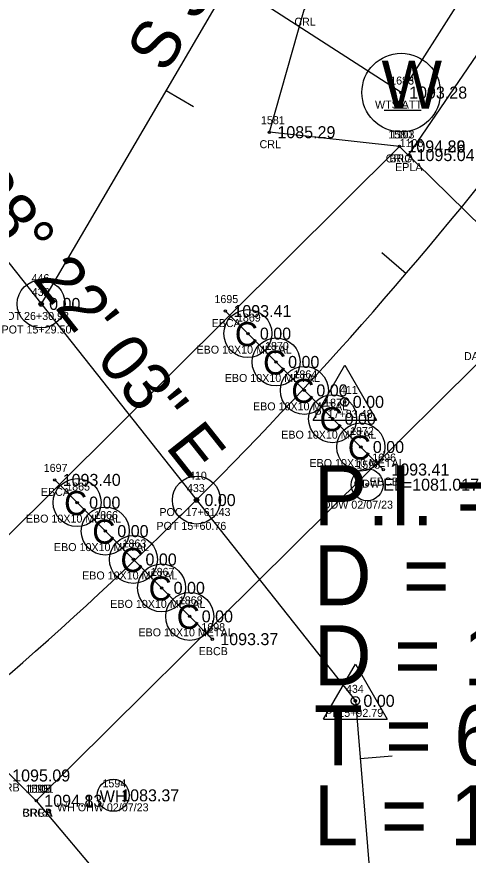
# Model space of a CAD drawing. Extents: x 1539151 to 1541799, y 1198646 to 1201165.
# Drawn here: x 1540107.9 to 1540164.3, y 1199420.8 to 1199525.6 of the extents above; entities that cross this region are included whole.
import ezdxf

# ---------------------------------------------------------------- set-up
doc = ezdxf.new("R2010")
doc.units = 0
for name, color, linetype in [('RD_EX_Bridge', 7, 'Continuous'), ('RD_EX_Bridge_txCode', 7, 'Continuous'), ('RD_EX_Driveway_txCode', 7, 'Continuous'), ('RD_EX_H2O', 7, 'Continuous'), ('RD_EX_H2O_txCode', 7, 'Continuous'), ('RD_EX_Road', 7, 'Continuous'), ('RD_EX_Road_txCode', 7, 'Continuous'), ('RD_EX_TX_Bridge_ELEV', 7, 'Continuous'), ('RD_EX_TX_H2O_ELEV', 7, 'Continuous'), ('RD_EX_TX_Road_ELEV', 7, 'Continuous'), ('RD_EX_TX_UT_ELEV', 7, 'Continuous'), ('RD_EX_TX_VEG_ELEV', 7, 'Continuous'), ('RD_EX_UT', 7, 'Continuous'), ('RD_EX_UT_txCode', 7, 'Continuous'), ('RD_EX_VEG', 7, 'Continuous'), ('RD_EX_VEG_txCode', 7, 'Continuous'), ('RD_HC_Cl', 7, 'Continuous'), ('RD_HC_Data', 7, 'Continuous'), ('RD_HC_Data_Tic', 7, 'Continuous'), ('RD_HC_Survey_ELEV', 7, 'Continuous'), ('RD_HC_txCode', 7, 'Continuous'), ('RD_SMD_Locator', 7, 'Continuous')]:
    doc.layers.add(name, color=color, linetype=linetype)

msp = doc.modelspace()

# ---------------------------------------------------------------- linework, layer by layer
at = {"layer": 'RD_EX_Bridge'}
for p, q in [((1540133.96, 1199488.77), (1540153.7, 1199468.96)), ((1540112.62, 1199467.67), (1540132.32, 1199447.76))]:
    msp.add_line(p, q, dxfattribs=at)
msp.add_lwpolyline([(1540110.32, 1199427.56), (1540091.92, 1199445.97), (1540155.71, 1199509.35), (1540174.37, 1199491.07), (1540110.32, 1199427.56)], dxfattribs=at)
for centre in [(1540136.77, 1199485.95), (1540140.3, 1199482.41), (1540143.83, 1199478.86), (1540147.36, 1199475.32), (1540150.89, 1199471.78), (1540115.43, 1199464.83), (1540118.95, 1199461.27), (1540122.47, 1199457.72), (1540125.99, 1199454.17), (1540129.5, 1199450.61)]:
    msp.add_circle(centre, 3, dxfattribs=at)
at = {"layer": 'RD_EX_H2O'}
for points in [[(1540155.71, 1199509.35), (1540139.46, 1199511.13), (1540143.81, 1199526.44), (1540162.16, 1199549.57), (1540173.51, 1199542.73), (1540200.09, 1199580.59)], [(1540110.32, 1199427.56), (1540119.33, 1199416.8), (1540132.83, 1199393.98), (1540138.31, 1199358.3), (1540135.73, 1199340.81)]]:
    msp.add_lwpolyline(points, dxfattribs=at)
for centre, radius in [((1540151.68, 1199467.07), 2), ((1540151.68, 1199467.07), 0.15), ((1540119.94, 1199428.24), 2), ((1540119.94, 1199428.24), 0.005)]:
    msp.add_circle(centre, radius, dxfattribs=at)
at = {"layer": 'RD_EX_Road'}
msp.add_lwpolyline([(1540156.86, 1199508.27), (1540186.51, 1199551.73), (1540214.32, 1199591.31), (1540249.72, 1199632.22), (1540286.8, 1199666.61), (1540324.36, 1199693.31), (1540344.92, 1199710.43), (1540367.33, 1199727.77), (1540402.7, 1199760.37), (1540437.37, 1199795.58), (1540455.74, 1199815.52), (1540466.15, 1199827.23), (1540503.86, 1199868.5), (1540538.69, 1199906.78), (1540571.44, 1199944.18), (1540603.42, 1199982.61), (1540638.15, 1200019.15), (1540672.1, 1200056.68), (1540705.32, 1200094.04), (1540739.01, 1200131.56)], dxfattribs=at)
at = {"layer": 'RD_EX_UT'}
msp.add_line((1540153.8, 1199513.88), (1540158.43, 1199513.88), dxfattribs=at)
msp.add_circle((1540155.93, 1199516.08), 4.91, dxfattribs=at)
at = {"layer": 'RD_EX_VEG'}
msp.add_lwpolyline([(1540712.01, 1200109.09), (1540564.8, 1199952.12), (1540511.25, 1199924.62), (1540488.55, 1199863.43), (1540394.02, 1199755.91), (1540277.54, 1199671.42), (1540233.54, 1199628.53), (1540200.18, 1199585.62), (1540155.93, 1199516.08), (1540069.9, 1199571.55)], dxfattribs=at)
at = {"layer": 'RD_HC_Cl'}
for p, q in [((1540172.44, 1199594.87), (1540110.93, 1199489.66)), ((1540078.23, 1199530.97), (1540150.21, 1199440.05)), ((1540150.21, 1199440.05), (1540160.06, 1199322.6))]:
    msp.add_line(p, q, dxfattribs=at)
msp.add_arc((1539789.52, 1199807.08), 482.77, 309.3443, 325.5923, dxfattribs=at)
at = {"layer": 'RD_HC_Data'}
for p, q in [((1540144.91, 1199475.13), (1540148.88, 1199482.01)), ((1540148.88, 1199482.01), (1540152.85, 1199475.13)), ((1540144.91, 1199475.13), (1540152.85, 1199475.13)), ((1540146.24, 1199437.75), (1540150.21, 1199444.63)), ((1540150.21, 1199444.63), (1540154.18, 1199437.75)), ((1540146.24, 1199437.75), (1540154.18, 1199437.75))]:
    msp.add_line(p, q, dxfattribs=at)
for centre, radius in [((1540110.93, 1199489.66), 3), ((1540110.93, 1199489.66), 3), ((1540110.93, 1199489.66), 0.282), ((1540110.93, 1199489.66), 0.282), ((1540148.88, 1199477.42), 0.529), ((1540130.34, 1199465.15), 3), ((1540130.34, 1199465.15), 3), ((1540130.34, 1199465.15), 0.282), ((1540130.34, 1199465.15), 0.282), ((1540150.21, 1199440.05), 0.529)]:
    msp.add_circle(centre, radius, dxfattribs=at)
at = {"layer": 'RD_HC_Data_Tic'}
for p, q in [((1540126.54, 1199516.36), (1540129.99, 1199514.34)), ((1540156.54, 1199493.44), (1540153.5, 1199496.04)), ((1540150.82, 1199432.86), (1540154.8, 1199433.19))]:
    msp.add_line(p, q, dxfattribs=at)
at = {"layer": 'RD_SMD_Locator'}
for centre in [(1540155.93, 1199516.08), (1540155.93, 1199516.08), (1540139.46, 1199511.13), (1540155.71, 1199509.35), (1540155.71, 1199509.35), (1540156.86, 1199508.27), (1540110.93, 1199489.66), (1540110.93, 1199489.66), (1540133.96, 1199488.77), (1540136.77, 1199485.95), (1540140.3, 1199482.41), (1540143.83, 1199478.86), (1540148.88, 1199477.42), (1540147.36, 1199475.32), (1540150.89, 1199471.78), (1540153.7, 1199468.96), (1540112.62, 1199467.67), (1540130.34, 1199465.15), (1540130.34, 1199465.15), (1540115.43, 1199464.83), (1540118.95, 1199461.27), (1540122.47, 1199457.72), (1540125.99, 1199454.17), (1540129.5, 1199450.61), (1540132.32, 1199447.76), (1540150.21, 1199440.05), (1540110.32, 1199427.56), (1540110.32, 1199427.56), (1540110.32, 1199427.56)]:
    msp.add_circle(centre, 0.15, dxfattribs=at)

# ---------------------------------------------------------------- texts
at = {"layer": 'RD_EX_Bridge'}
for p in [(1540135.14, 1199484.39), (1540138.67, 1199480.84), (1540142.2, 1199477.3), (1540145.73, 1199473.76), (1540149.26, 1199470.22), (1540113.8, 1199463.27), (1540117.32, 1199459.71), (1540120.84, 1199456.16), (1540124.36, 1199452.6), (1540127.87, 1199449.05)]:
    msp.add_text('C', height=3, dxfattribs=at).set_placement(p)
at = {"layer": 'RD_EX_Bridge_txCode'}
for s, p in [('1103', (1540154.61, 1199510.35)), ('BRC', (1540154.46, 1199507.35)), ('1695', (1540132.59, 1199489.77)), ('1869', (1540135.4, 1199487.45)), ('EBCA', (1540132.24, 1199486.77)), ('EBO 10X10 METAL', (1540130.35, 1199483.45)), ('1870', (1540138.91, 1199483.91)), ('EBO 10X10 METAL', (1540133.88, 1199479.91)), ('1864', (1540142.46, 1199480.36)), ('1871', (1540146.3, 1199476.82)), ('EBO 10X10 METAL', (1540137.41, 1199476.36)), ('EBO 10X10 METAL', (1540140.94, 1199472.82)), ('1872', (1540149.54, 1199473.28)), ('1696', (1540152.31, 1199469.96)), ('1697', (1540111.25, 1199468.67)), ('EBO 10X10 METAL', (1540144.47, 1199469.28)), ('1865', (1540114.06, 1199466.33)), ('EBCB', (1540152, 1199466.96)), ('EBCA', (1540110.9, 1199465.67)), ('EBO 10X10 METAL', (1540109.02, 1199462.33)), ('1866', (1540117.56, 1199462.77)), ('1863', (1540121.1, 1199459.22)), ('EBO 10X10 METAL', (1540112.53, 1199458.77)), ('EBO 10X10 METAL', (1540116.05, 1199455.22)), ('1867', (1540124.62, 1199455.67)), ('EBO 10X10 METAL', (1540119.57, 1199451.67)), ('1868', (1540128.13, 1199452.11)), ('1698', (1540130.95, 1199448.76)), ('EBO 10X10 METAL', (1540123.09, 1199448.11)), ('EBCB', (1540130.62, 1199445.76)), ('1105', (1540109.22, 1199428.56)), ('1101', (1540109.5, 1199428.56)), ('BRCA', (1540108.58, 1199425.56)), ('BRCB', (1540108.6, 1199425.56))]:
    msp.add_text(s, height=1, dxfattribs=at).set_placement(p)
at = {"layer": 'RD_EX_Driveway_txCode'}
msp.add_text('DA GRAVEL', height=1, dxfattribs=at).set_placement((1540163.78, 1199482.64))
at = {"layer": 'RD_EX_H2O'}
for s, height, p in [('ODW', 1, (1540150.01, 1199466.7)), ('WH', 1.5, (1540118.26, 1199427.36))]:
    msp.add_text(s, height=height, dxfattribs=at).set_placement(p)
at = {"layer": 'RD_EX_H2O_txCode'}
for s, p in [('CRL', (1540142.58, 1199524.44)), ('1581', (1540138.4, 1199512.13)), ('1580', (1540154.32, 1199510.35)), ('CRL', (1540138.23, 1199509.13)), ('CRLA', (1540153.99, 1199507.35)), ('1593', (1540150.33, 1199469.07)), ('ODW 02/07/23', (1540146.06, 1199464.07)), ('1595', (1540108.97, 1199428.56)), ('1594', (1540118.59, 1199429.24)), ('CRRA', (1540108.58, 1199425.56)), ('WH OHW 02/07/23', (1540112.91, 1199426.24))]:
    msp.add_text(s, height=1, dxfattribs=at).set_placement(p)
at = {"layer": 'RD_EX_Road_txCode'}
for s, p in [('1106', (1540155.73, 1199509.27)), ('EPLA', (1540155.17, 1199506.27)), ('EPRB', (1540104.61, 1199428.72))]:
    msp.add_text(s, height=1, dxfattribs=at).set_placement(p)
at = {"layer": 'RD_EX_TX_Bridge_ELEV'}
for s, p in [('1094.89', (1540156.71, 1199508.6)), ('1093.41', (1540134.96, 1199488.02)), ('0.00', (1540138.27, 1199485.2)), ('0.00', (1540141.8, 1199481.66)), ('0.00', (1540145.33, 1199478.11)), ('0.00', (1540148.86, 1199474.57)), ('0.00', (1540152.39, 1199471.03)), ('1093.41', (1540154.7, 1199468.21)), ('1093.40', (1540113.62, 1199466.92)), ('0.00', (1540116.93, 1199464.08)), ('0.00', (1540120.45, 1199460.52)), ('0.00', (1540123.97, 1199456.97)), ('0.00', (1540127.49, 1199453.42)), ('0.00', (1540131, 1199449.86)), ('1093.37', (1540133.32, 1199447.01)), ('1094.83', (1540111.32, 1199426.81)), ('1094.83', (1540111.32, 1199426.81))]:
    msp.add_text(s, height=1.5, dxfattribs=at).set_placement(p)
at = {"layer": 'RD_EX_TX_H2O_ELEV'}
for s, p in [('1085.29', (1540140.46, 1199510.38)), ('1094.26', (1540156.71, 1199508.6)), ('EL=1081.017', (1540153.68, 1199466.32)), ('1083.37', (1540120.94, 1199427.49)), ('1094.13', (1540111.32, 1199426.81))]:
    msp.add_text(s, height=1.5, dxfattribs=at).set_placement(p)
at = {"layer": 'RD_EX_TX_Road_ELEV'}
for s, p in [('1095.04', (1540157.86, 1199507.52)), ('1095.09', (1540107.31, 1199429.97))]:
    msp.add_text(s, height=1.5, dxfattribs=at).set_placement(p)
at = {"layer": 'RD_EX_TX_UT_ELEV'}
msp.add_text('1093.28', height=1.5, dxfattribs=at).set_placement((1540156.93, 1199515.33))
at = {"layer": 'RD_EX_TX_VEG_ELEV'}
msp.add_text('1093.28', height=1.5, dxfattribs=at).set_placement((1540156.93, 1199515.33))
at = {"layer": 'RD_EX_UT'}
msp.add_text('W', height=6, dxfattribs=at).set_placement((1540153.47, 1199514.08))
at = {"layer": 'RD_EX_UT_txCode'}
for s, p in [('1685', (1540154.56, 1199517.08)), ('WTS ATT', (1540152.66, 1199514.08))]:
    msp.add_text(s, height=1, dxfattribs=at).set_placement(p)
at = {"layer": 'RD_EX_VEG_txCode'}
for s, p in [('1683', (1540154.56, 1199517.08)), ('TL', (1540155.16, 1199514.08))]:
    msp.add_text(s, height=1, dxfattribs=at).set_placement(p)
at = {"layer": 'RD_HC_Data'}
for s, rotation, p in [('S 30%%d 18\' 48" W', 59.6867, (1540126.53, 1199518.32)), ('S 38%%d 22\' 03" E', 308.3675, (1540096.16, 1199509.93))]:
    msp.add_text(s, height=6, rotation=rotation, dxfattribs=at).set_placement(p)
for s, p in [('P.I. = 17+83.48', (1540145, 1199462)), ('D', (1540145, 1199452)), ('    = 16%%d 14\' 53" (LT)', (1540145, 1199452)), ('D = 11%%d 52\' 05"', (1540145, 1199442)), ("T = 68.91'", (1540145, 1199432)), ("L = 136.90'", (1540145, 1199422))]:
    msp.add_text(s, height=7.5, dxfattribs=at).set_placement(p)
at = {"layer": 'RD_HC_Survey_ELEV'}
for p in [(1540111.93, 1199488.91), (1540111.93, 1199488.91), (1540149.88, 1199476.67), (1540131.34, 1199464.4), (1540131.34, 1199464.4), (1540151.21, 1199439.3)]:
    msp.add_text('0.00', height=1.5, dxfattribs=at).set_placement(p)
at = {"layer": 'RD_HC_txCode'}
for s, p in [('446', (1540109.73, 1199492.39)), ('432', (1540109.75, 1199490.66)), ('POT 26+30.93', (1540105.67, 1199487.66)), ('POT 15+29.50', (1540105.98, 1199485.97)), ('411', (1540148.27, 1199478.42)), ('PI 17+83.48', (1540145.1, 1199475.42)), ('410', (1540129.4, 1199467.7)), ('433', (1540129.15, 1199466.15)), ('POC 17+61.43', (1540125.71, 1199463.15)), ('POT 15+60.76', (1540125.34, 1199461.42)), ('434', (1540149.03, 1199441.05)), ('PI 15+92.79', (1540146.43, 1199438.05))]:
    msp.add_text(s, height=1, dxfattribs=at).set_placement(p)

doc.saveas('drawing.dxf')
